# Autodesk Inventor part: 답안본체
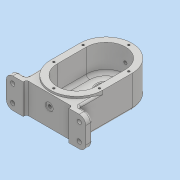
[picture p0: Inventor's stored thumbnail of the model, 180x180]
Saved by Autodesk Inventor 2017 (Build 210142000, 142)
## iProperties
Part Number: 답안본체
Material: 일반
Document SubType Name: Modeling
Designer: MRC
Density: 1 g/cm^3
Appearance: 기본값
Author: MRC
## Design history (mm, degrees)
sketch "스케치1"
  geometry: L1 (0, 0)-(0, -45); L2 (-40, 0)-(-40, -45); L3 (40, -45)-(40, 0); A1 r 40 centre (0, 0) between (40, 0) and (-40, 0); A2 r 40 centre (0, -45) between (-40, -45) and (40, -45); 2 further points
  constraints: 8 end point, 4 point on circle, 4 tangent, 2 centre point, 1 coincident, 1 midpoint, 1 parallel, 1 vertical
  dimensions: "d0" = 80 distance between parallel lines of L3 L2; "d1" = 45 distance of L1.end L1.start
extrude "돌출1" new body sketch "스케치1" stored distance "d2" = 49; taper "d3" = 0 deg
sketch "스케치2"
  geometry: L1 (-40, 0)-(-40, -45) reference; L2 (40, -45)-(40, 0) reference; L3 (-30, 0)-(-30, -45); L4 (30, -45)-(30, 0); A1 r 40 centre (0, -45) between (-40, -45) and (40, -45) reference; A2 r 40 centre (0, 0) between (40, 0) and (-40, 0) reference; A3 r 30 centre (0, -45) between (-30, -45) and (30, -45); A4 r 30 centre (0, 0) between (30, 0) and (-30, 0)
  constraints: 4 end point, 4 point on circle, 2 centre point, 3 other
  dimensions: "d4" = 10 radial gap between concentric circles of A2 A4
extrude "돌출2" cut sketch "스케치2" distance "d5" = 41; taper "d6" = 0 deg
sketch "스케치3"
  geometry: L1 (0, 0)-(0, -45); L2 (-26, 0)-(-26, -45); L3 (26, -45)-(26, 0); A1 r 40 centre (0, 0) between (40, 0) and (-40, 0) reference; A2 r 26 centre (0, 0) between (26, 0) and (-26, 0); A3 r 26 centre (0, -45) between (-26, -45) and (26, -45); 1 further point
  constraints: 8 end point, 4 point on circle, 4 tangent, 2 centre point, 1 midpoint, 1 parallel, 1 vertical
  dimensions: "d7" = 52 distance between parallel lines of L3 L2; "d8" = 45 distance of L1.end L1.start
extrude "돌출3" join sketch "스케치3" distance "d9" = 11; taper "d10" = 0 deg
sketch "스케치4"
  geometry: L1 (-26, 0)-(-26, -45) reference; L2 (26, -45)-(26, 0) reference; L3 (-26, 0)-(-26, -30); L4 (-26, -30)-(26, -30); L5 (26, 0)-(26, -45) reference; L6 (26, 0)-(26, -30); A1 r 26 centre (0, 0) between (26, 0) and (-26, 0) reference; A2 r 26 centre (0, 0) between (26, 0) and (-26, 0)
  constraints: 6 end point, 2 point on circle, 2 point on line, 1 centre point, 1 coincident, 1 collinear, 1 perpendicular
  dimensions: "d11" = 30 distance of L1.start L3.end
extrude "돌출4" cut sketch "스케치4" distance "d12" = 3; taper "d13" = 0 deg
sketch "스케치5"
  geometry: A1 r 26 centre (0, 0) between (26, 0) and (-26, 0) reference
hole "구멍1" sketch "스케치5" at (0, 0) diameter "d14" = 22; stored, may be unused: countersink angle "d18" = 90 deg, drill point angle "d20" = 118 deg; dims "d15" = 6, "d16" = 28, "d17" = 4, "d19" = 8
sketch "스케치6"
  geometry: A1 r 30 centre (0, -45) between (-30, -45) and (30, -45) reference
hole "구멍2" sketch "스케치6" diameter "d21" = 20; stored, may be unused: countersink angle "d25" = 90 deg, drill point angle "d27" = 0 deg; dims "d22" = 6, "d23" = 28, "d24" = 8, "d26" = 12
sketch "스케치7"
  geometry: C1 r 11 at (0, 0) reference
hole "구멍3" sketch "스케치7" at (0, 0) diameter "d28" = 28; stored, may be unused: countersink angle "d32" = 90 deg, drill point angle "d34" = 0 deg; dims "d29" = 6, "d30" = 28, "d31" = 8, "d33" = 8
node "작업 평면2"
sketch "스케치8"
  geometry: L1 (51, -24.5)-(-51, -24.5); L2 (-61, -14.5)-(-61, 11.5); L3 (-51, 21.5)-(51, 21.5); L4 (61, 11.5)-(61, -14.5); L5 (-40, -24.5)-(40, -24.5) reference; L6 (40, -24.5)-(40, 24.5) reference; L7 (40, -24.5)-(-40, -24.5); L8 (-40, -24.5)-(-40, 21.5); L9 (-40, 21.5)-(40, 21.5); L10 (40, 21.5)-(40, -24.5); A1 r 10 centre (51, -14.5) between (51, -24.5) and (61, -14.5); A2 r 10 centre (51, 11.5) between (61, 11.5) and (51, 21.5); A3 r 10 centre (-51, 11.5) between (-51, 21.5) and (-61, 11.5); A4 r 10 centre (-51, -14.5) between (-61, -14.5) and (-51, -24.5); 2 further points
  constraints: 16 end point, 8 point on circle, 8 tangent, 4 centre point, 4 parallel, 3 equal radius, 2 horizontal, 2 midpoint, 2 perpendicular, 1 point on line
  dimensions: "d37" = 46 distance between parallel lines of L3 L1; "d38" = 122 distance between parallel lines of L2 L4; "d39" = 10 radius of A1 (derived); "d42" = 80 distance between parallel lines of L8 L10
extrude "돌출5" join sketch "스케치8" distance "d40" = 10; taper "d41" = 0 deg
extrude "돌출6" join sketch "스케치8" stored distance "d43" = 10; taper "d44" = 0 deg
sketch "스케치9"
  geometry: A1 r 10 centre (-51, 14.5) between (-51, 24.5) and (-61, 14.5) reference; A2 r 10 centre (-51, -11.5) between (-61, -11.5) and (-51, -21.5) reference; A3 r 10 centre (51, 14.5) between (61, 14.5) and (51, 24.5) reference; A4 r 10 centre (51, -11.5) between (51, -21.5) and (61, -11.5) reference; 5 further points
  constraints: 4 coincident
hole "구멍4" sketch "스케치9" at (-51, 14.5), (-51, -11.5), (51, -11.5), (51, 14.5) diameter "d45" = 6.6; stored, may be unused: countersink angle "d49" = 90 deg, drill point angle "d51" = 0 deg; dims "d46" = 6, "d47" = 11, "d48" = 2, "d50" = 8
sketch "스케치10"
  geometry: A1 r 30 centre (0, 0) between (30, 0) and (-30, 0) reference; 1 further point
  constraints: 1 vertical alignment
  dimensions: "d52" = 35 distance of A1.centre point (0, 35)
hole "구멍5" sketch "스케치10" at (0, 35) diameter "d53" = 3.242; stored, may be unused: countersink angle "d57" = 90 deg, drill point angle "d59" = 118 deg; dims "d54" = 8, "d55" = 11, "d56" = 2, "d58" = 10
sketch "스케치11"
  geometry: A1 r 30 centre (0, -45) between (-30, -45) and (30, -45) reference; 1 further point
  constraints: 1 vertical alignment
  dimensions: "d63" = 35 distance of point (0, -80) A1.centre
hole "구멍6" sketch "스케치11" at (0, -80) diameter "d64" = 3.242; stored, may be unused: countersink angle "d68" = 90 deg, drill point angle "d70" = 118 deg; dims "d65" = 8, "d66" = 11, "d67" = 2, "d69" = 10
sketch "스케치12"
  geometry: L1 (51, 21.5)-(-51, 21.5) reference; L2 (-51, -24.5)-(51, -24.5) reference; L3 (-35, 21.5)-(35, 21.5); L4 (35, 21.5)-(35, -24.5); L5 (35, -24.5)-(-35, -24.5); L6 (-35, -24.5)-(-35, 21.5); 2 further points
  constraints: 8 end point, 2 midpoint, 2 parallel, 2 point on line, 1 horizontal, 1 perpendicular
  dimensions: "d74" = 70 distance between parallel lines of L4 L6
extrude "돌출7" cut sketch "스케치12" distance "d75" = 5; taper "d76" = 0 deg
sketch "스케치13"
  geometry: C1 r 14 at (0, 0) reference; 1 further point
  constraints: 1 vertical alignment
  dimensions: "d77" = 20 distance of C1.centre point (0, 20)
hole "구멍7" sketch "스케치13" at (0, 20) diameter "d78" = 3.242; stored, may be unused: countersink angle "d82" = 90 deg, drill point angle "d84" = 118 deg; dims "d79" = 8, "d80" = 11, "d81" = 2, "d83" = 10
fillet "모깎기1" dims "d88" = 5
sketch "스케치14"
  geometry: L1 (40, 24.5)-(-40, 24.5) reference; 2 further points
  constraints: 1 vertical alignment
  dimensions: "d132" = 21 distance from line of L1 point (0, 3.5)
hole "구멍8" sketch "스케치14" at (0, 3.5) diameter "d90" = 4.917; stored, may be unused: countersink angle "d94" = 90 deg, drill point angle "d96" = 0 deg; dims "d91" = 12, "d92" = 12, "d93" = 1, "d95" = 17.1
fillet "모깎기2" dims "d97" = 3
fillet "모깎기3" dims "d98" = 0.3
chamfer "모따기1" distance "d99" = 1; stored, may be unused: second distance "d100" = 2, angle "d101" = 45 deg
node "작업 평면3"
sketch "스케치15"
  geometry: L1 (40, 24.5)-(-40, 24.5) reference; C1 r 6 at (0, 3.5); 1 further point
  constraints: 1 centre point, 1 midpoint, 1 vertical alignment
  dimensions: "d120" = 12 diameter of C1; "d121" = 21 distance of C1.centre point (0, 24.5)
extrude "돌출8" join sketch "스케치15" stored distance "d104" = 5; taper "d105" = 0 deg
fillet "모깎기4" dims "d115" = 3
sketch "스케치16"
  geometry: L1 (-35, -92)-(-51, -92) reference; A1 r 37 centre (0, 0) between (37, 0) and (-37, 0) reference; 1 further point
  constraints: 1 vertical alignment, 1 other
  dimensions: "d116" = 12 distance from line of point (0, -80) L1
feature "엠보싱1" sketch "스케치16" dims "d117" = 0.5, "d118" = 0
fillet "모깎기5" dims "d122" = 3
hole "구멍10" diameter "d125" = 4.917; stored, may be unused: countersink angle "d129" = 90 deg, drill point angle "d131" = 0 deg; dims "d123" = 10, "d124" = 10, "d126" = 12, "d127" = 12, "d128" = 1, "d130" = 17.1
node "솔리드1"
pattern_circular "원형 패턴1" dims angle "d61" = 180 deg
pattern_circular "원형 패턴2" dims angle "d72" = 180 deg
pattern_circular "원형 패턴3" dims angle "d86" = 360 deg
other parameters: "d36" = -92, "d102" = -135
